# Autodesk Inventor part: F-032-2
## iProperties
Author: Andy Mckenna
Shininess: 25.0
Angle Display Precision: 2
Document Length Units: 11272
Document Angle Units: 11286
Document Time Units: 11279
Document Mass Units: 11290
Document Length Units Precision: 3
Document Angle Units Precision: 2
Compacted: True
PropertySet Name: _Private Model Information
Created: 2001-09
Part Number: F-032-2
Material: Stainless Steel, Austenitic
Description: PEM Flush Fastener, F-032-2
Document SubType Name: Modeling
Designer: Andy Mckenna
Control State: 0
Master: False
Checked Out: False
PropertySet Name: Design Tracking Control
Density: 7.84
Volumn: 0.17245559573138858
Area: 3.4800931280430336
PropertySet Name: Model Information
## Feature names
1. Extrusion1
2. Extrusion2
3. Revolution1
4. Hole1
5. Chamfer3
6. Chamfer4
7. Chamfer5
